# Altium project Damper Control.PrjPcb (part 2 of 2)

## Sheet Interface and Peripherals.SchDoc
size A3; Date: Not shown in title block; ApprovedBy: Not shown in title block; CheckedBy: Not shown in title block; Author: Not shown in title block; CompanyName: Not shown in title block; Engineer: Not shown in title block; Organization: Not shown in title block; Address1: Not shown in title block; Address2: Not shown in title block; Address3: Not shown in title block; Address4: Not shown in title block; DocumentNumber: 4; Revision: Use project parameter SCH_Rev; SheetNumber: 4; SheetTotal: 5; PageSetup: Record=PageOptions¦CenterHorizontal=True¦CenterVertical=True¦PrintScale=0.69¦XCorrection=1.00¦YCorrection=1.00¦PrintKind=0¦BorderSize=5000000¦LeftOffset=0¦BottomOffset=0¦Orientation=2¦PaperLength=1000¦PaperWidth=1000¦Scale=100¦PaperSource=15¦PrintQuality=600¦MediaType=1¦DitherType=10¦PaperKind=Letter¦PrintScaleMode=1
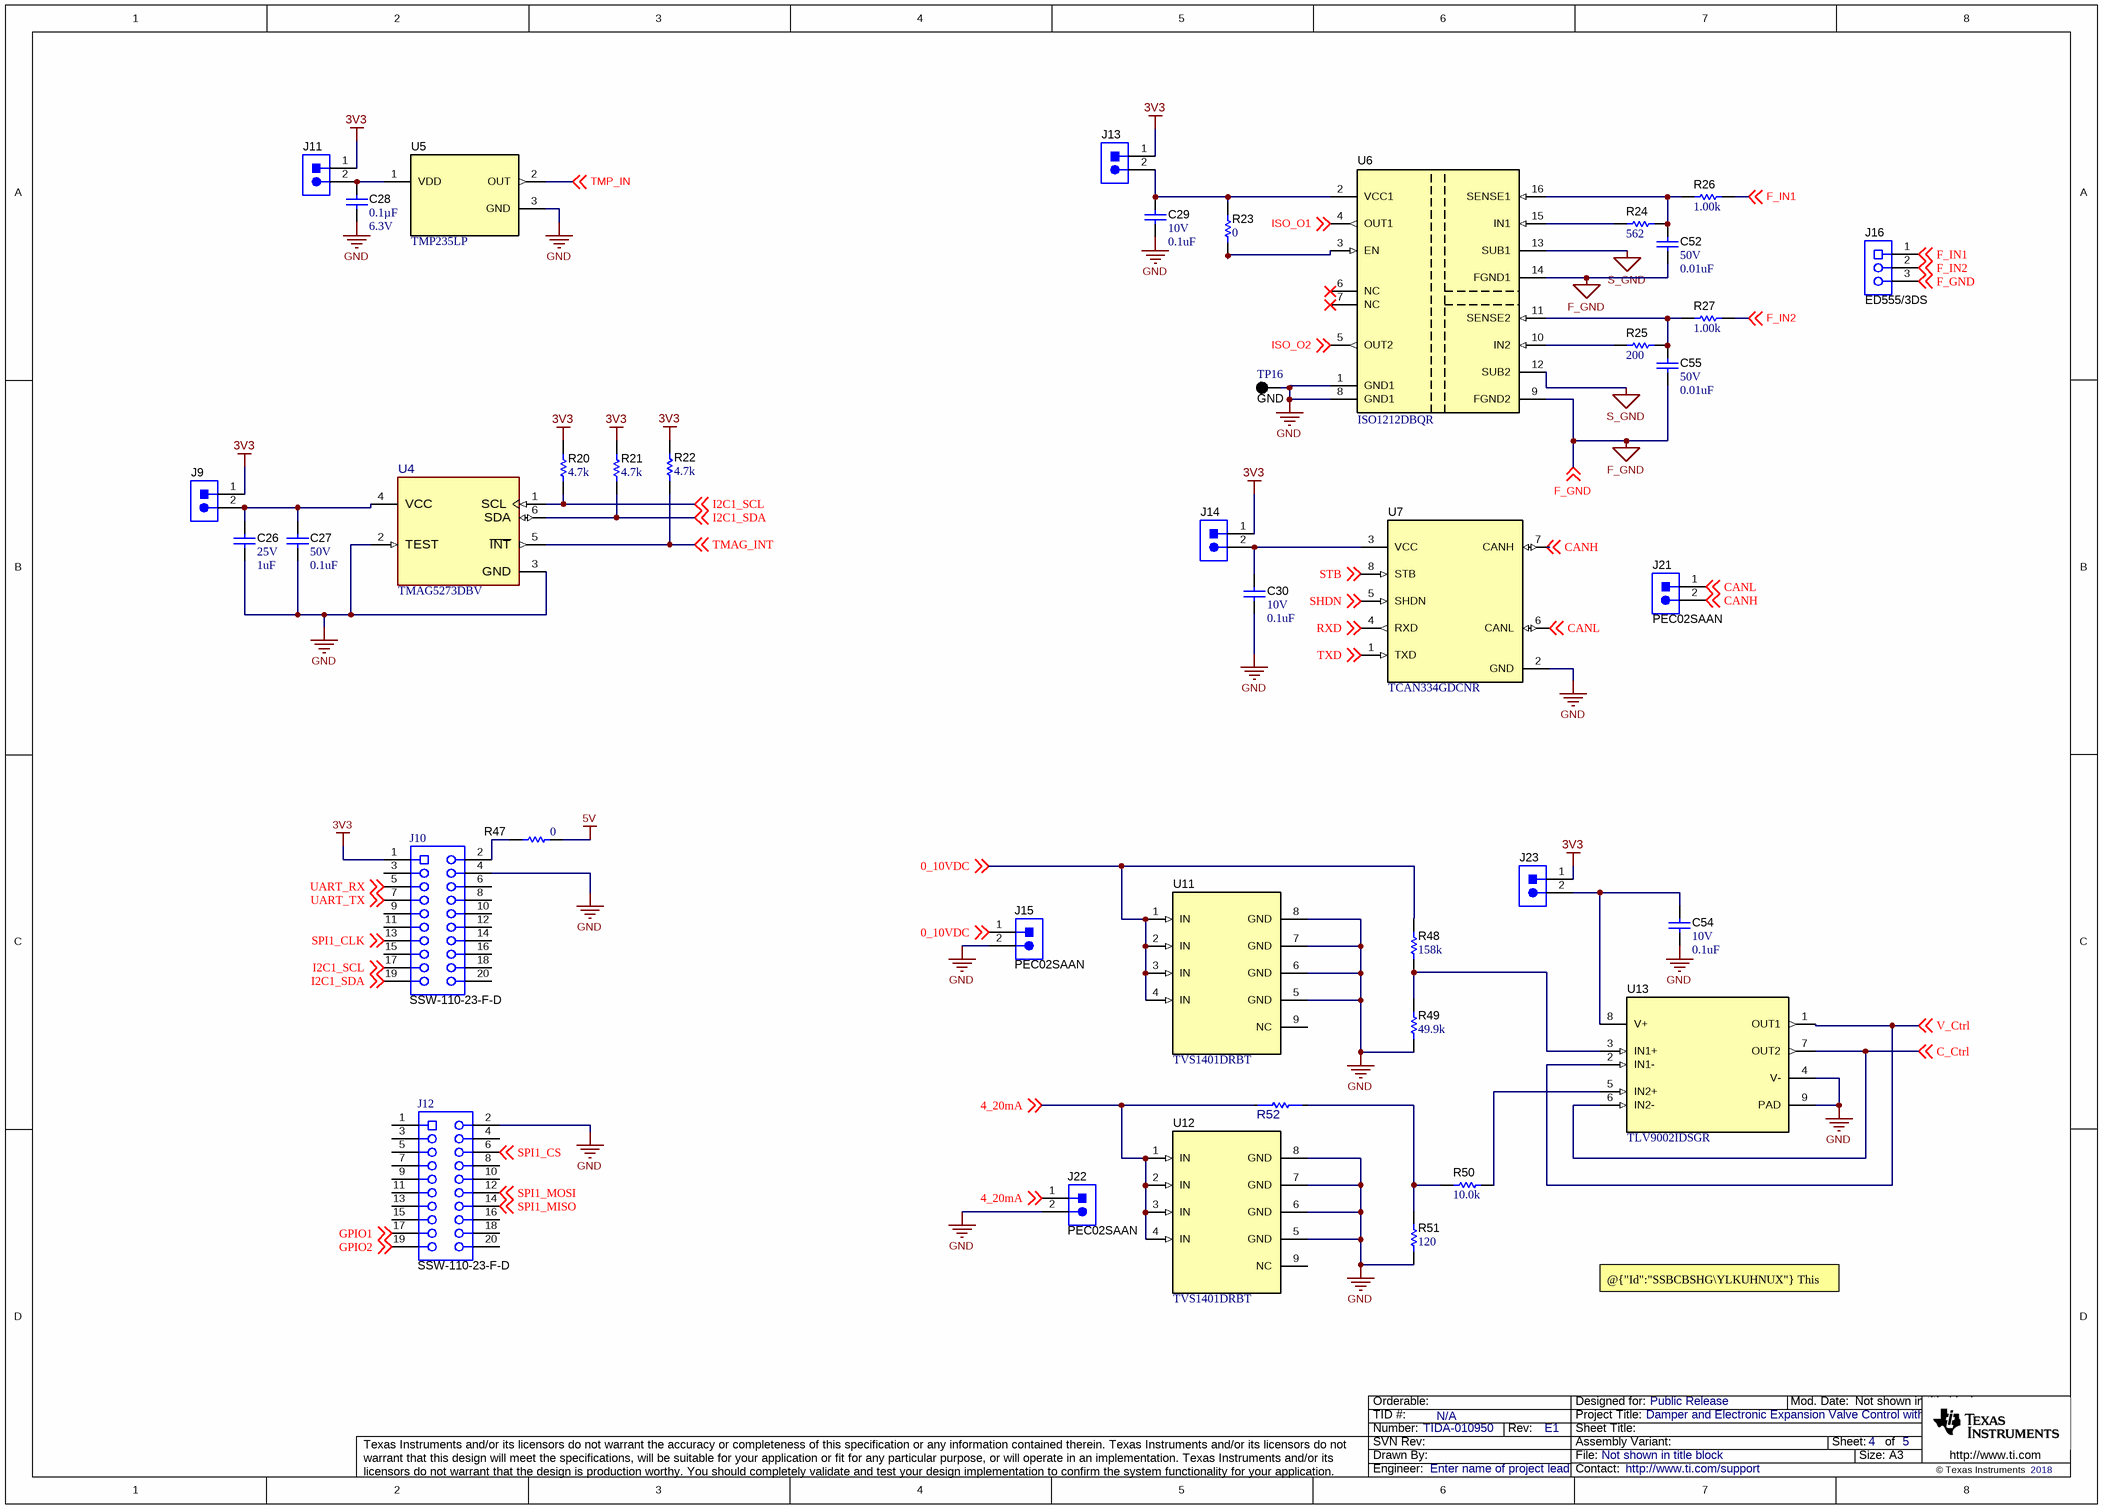
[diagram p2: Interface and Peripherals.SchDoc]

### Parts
(Parts that share a designator on the sheet are numbered #1, #2 ... from top to bottom, then left to right.)
C26  VDC_V: 25V  ValueDisplayed: 1uF  [0402]  (hidden comment: GRM155R61E105KA12D)
C27  VDC_V: 50V  ValueDisplayed: 0.1uF  [0402]  (hidden comment: GRM155R71H104ME14D)
C28  ValueDisplayed: 0.1µF  VDC_V: 6.3V  [0603]  (hidden comment: C0603C104K9PAC7867)
C29  VDC_V: 10V  ValueDisplayed: 0.1uF  [0402]  (hidden comment: GRM155R61A104KA01D)
C30  VDC_V: 10V  ValueDisplayed: 0.1uF  [0402]  (hidden comment: GRM155R61A104KA01D)
C52  VDC_V: 50V  ValueDisplayed: 0.01uF  [0402]  (hidden comment: GRM155R71H103KA88D)
C54#1  VDC_V: 10V  ValueDisplayed: 0.1uF  [0402]  (hidden comment: GRM155R61A104KA01D)
C55  VDC_V: 50V  ValueDisplayed: 0.01uF  [0402]  (hidden comment: GRM155R71H103KA88D)
J9  M20-8770246  [Harwin_M20-87702]  (value not drawn)
J10  SSW-110-23-F-D  [CONN_SSW-110-23-F-D]
J11  M20-8770246  [Harwin_M20-87702]  (value not drawn)
J12  SSW-110-23-F-D  [CONN_SSW-110-23-F-D]
J13  M20-8770246  [Harwin_M20-87702]  (value not drawn)
J14  M20-8770246  [Harwin_M20-87702]  (value not drawn)
J15#1  PEC02SAAN  [CONN_PEC02SAAN]
J16  ED555/3DS  [TERM_BLK_ED555-3DS]
J21  PEC02SAAN  [CONN_PEC02SAAN]
J22#1  PEC02SAAN  [CONN_PEC02SAAN]
J23#1  M20-8770246  [Harwin_M20-87702]  (value not drawn)
R20  ValueDisplayed: 4.7k  [0201]  (hidden comment: RC0201JR-7D4K7L)
R21  ValueDisplayed: 4.7k  [0201]  (hidden comment: RC0201JR-7D4K7L)
R22  ValueDisplayed: 4.7k  [0201]  (hidden comment: RC0201JR-7D4K7L)
R23  ValueDisplayed: 0  [0603]  (hidden comment: CRCW06030000Z0EA)
R24  ValueDisplayed: 562  [0805_HV]  (hidden comment: RG2012P-5620-B-T5)
R25  ValueDisplayed: 200  [0603]  (hidden comment: RT0603DRE07200RL)
R26  ValueDisplayed: 1.00k  [1206]  (hidden comment: RP73D2B1K0BTG)
R27  ValueDisplayed: 1.00k  [1206]  (hidden comment: RP73D2B1K0BTG)
R47  ValueDisplayed: 0  [0603]  (hidden comment: CRCW06030000Z0EA)
R48#1  ValueDisplayed: 158k  [0402]  (hidden comment: CRCW0402158KFKED)
R49#1  ValueDisplayed: 49.9k  [0402]  (hidden comment: CRCW040249K9FKED)
R50#1  ValueDisplayed: 10.0k  [0402]  (hidden comment: CRCW040210K0FKED)
R51#1  ValueDisplayed: 120  [2512]  (hidden comment: CRCW2512120RFKEG)
R52#1  TNPW060312K0BYEN  [FP-TNPW060312K0BYEN_0603-MFG]  (value not drawn)
TP16  GND  [Keystone5001]
U4  TMAG5273DBV  [DBV0006A-MFG]
U5  TMP235LP  [LP0003A]
U6  ISO1212DBQR  [DBQ0016A_N]
U7  TCAN334GDCNR  [DCN0008A_N]
U11#1  TVS1401DRBT  [DRB0008A]
U12#1  TVS1401DRBT  [DRB0008A]
U13#1  TLV9002IDSGR  [DSG0008A]

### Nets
3V3: J9.1 J10.1 J11.1 J13.1 J14.1 J23#1.1 R20.2 R21.2 R22.2
5V: R47.2
F_GND: C52.2 C55.2 J16.3 U6.9(FGND2) U6.14(FGND1) ; off-sheet F_GND
GND: C26.2 C27.2 C28.2 C29.2 C30.2 C54#1.1 J10.4 J12.2 J15#1.2 J22#1.2 R49#1.1 R51#1.1 TP16.1 U4.2(TEST) U4.3(GND) U5.3(GND) U6.1(GND1) U6.8(GND1) U7.2(GND) U11#1.5(GND) U11#1.6(GND) U11#1.7(GND) U11#1.8(GND) U12#1.5(GND) U12#1.6(GND) U12#1.7(GND) U12#1.8(GND) U13#1.4(V-) U13#1.9(PAD)
S_GND: U6.12(SUB2) U6.13(SUB1)
0_10VDC: J15#1.1 R48#1.2 U11#1.1(IN) U11#1.2(IN) U11#1.3(IN) U11#1.4(IN) ; off-sheet 0_10VDC
4_20mA: J22#1.1 R52#1.1 U12#1.1(IN) U12#1.2(IN) U12#1.3(IN) U12#1.4(IN) ; off-sheet 4_20mA
C_Ctrl: U13#1.6(IN2-) U13#1.7(OUT2) ; off-sheet C_Ctrl
CANH: J21.2 U7.7(CANH) ; off-sheet CANH
CANL: J21.1 U7.6(CANL) ; off-sheet CANL
F_IN1: J16.1 R26.2 ; off-sheet F_IN1
F_IN2: J16.2 R27.2 ; off-sheet F_IN2
GPIO1: J12.17 ; off-sheet GPIO1
GPIO2: J12.19 ; off-sheet GPIO2
I2C1_SCL: J10.17 R20.1 U4.1(SCL) ; off-sheet I2C1_SCL
I2C1_SDA: J10.19 R21.1 U4.6(SDA) ; off-sheet I2C1_SDA
ISO_O1: U6.4(OUT1) ; off-sheet ISO_O1
ISO_O2: U6.5(OUT2) ; off-sheet ISO_O2
RXD: U7.4(RXD) ; off-sheet RXD
SHDN: U7.5(SHDN) ; off-sheet SHDN
SPI1_CLK: J10.13 ; off-sheet SPI1_CLK
SPI1_CS: J12.6 ; off-sheet SPI1_CS
SPI1_MISO: J12.14 ; off-sheet SPI1_MISO
SPI1_MOSI: J12.12 ; off-sheet SPI1_MOSI
STB: U7.8(STB) ; off-sheet STB
TMAG_INT: R22.1 U4.5(~{INT}) ; off-sheet TMAG_INT
TMP_IN: U5.2(OUT) ; off-sheet TMP_IN
TXD: U7.1(TXD) ; off-sheet TXD
UART_RX: J10.5 ; off-sheet UART_RX
UART_TX: J10.7 ; off-sheet UART_TX
V_Ctrl: U13#1.1(OUT1) U13#1.2(IN1-) ; off-sheet V_Ctrl
NetC26_1: C26.1 C27.1 J9.2 U4.4(VCC)
NetC28_1: C28.1 J11.2 U5.1(VDD)
NetC29_1: C29.1 J13.2 R23.2 U6.2(VCC1)
NetC30_1: C30.1 J14.2 U7.3(VCC)
NetC52_1: C52.1 R24.2 R26.1 U6.16(SENSE1)
NetC54#1_2: C54#1.2 J23#1.2 U13#1.8(V+)
NetC55_1: C55.1 R25.2 R27.1 U6.11(SENSE2)
NetJ10_2: J10.2 R47.1
NetR23_1: R23.1 U6.3(EN)
NetR24_1: R24.1 U6.15(IN1)
NetR25_1: R25.1 U6.10(IN2)
NetR48#1_1: R48#1.1 R49#1.2 U13#1.3(IN1+)
NetR50#1_1: R50#1.1 U13#1.5(IN2+)
NetR50#1_2: R50#1.2 R51#1.2 R52#1.2

Not connected (* = marked no-connect by the designer): J10 3 6 8 9 10 11 12 14 15 16 18 20; J12 1 3 4 5 7 8 9 10 11 13 15 16 18 20; U6 6(NC)* 7(NC)*; U11#1 9(NC); U12#1 9(NC)

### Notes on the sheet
- @{"Id":"SSBCBSHG\YLKUHNUX"} This should be PRG18BB470MB1RB

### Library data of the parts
C26 = CMP-0006608-2: CAP, CERM, 1 uF, 25 V, +/- 10%, X5R, 0402; Manufacturer: MuRata; TaMin_C: -55°C; Polarized: N; SizeAreaWB_mm2: 3; Value1: Unknown; U/M: EA; Value: 1uF; TaMax_C: 85°C; SizeZ_mm: 0.6; SizeX_mm: 1; SizeY_mm: 0.5; Cap_F: 1µF; AEC Category: Q200
C27 = CMP-0006675-2: CAP, CERM, 0.1 uF, 50 V, +/- 20%, X7R, 0402; Manufacturer: MuRata; TaMin_C: -55°C; Polarized: N; SizeAreaWB_mm2: 3; Value1: Unknown; U/M: EA; Value: 0.1uF; TaMax_C: 125°C; SizeZ_mm: 0.6; SizeX_mm: 1; SizeY_mm: 0.5; Cap_F: 100nF; AEC Category: Q200
C28 = CMP-0085846-1: CAP, CERM, 0.1 µF, 6.3 V,+/- 10%, X5R, 0603; Manufacturer: Kemet; SizeAreaWB_mm2: 4.68; SizeArea_mm2: 1.28; SizeZ_mm: 1; Polarized: N; Cap_F: 100nF; TaMin_C: -55°C; AEC Category: Q200; SizeX_mm: 1.6; Value: 0.1uF; U/M: EA; SizeY_mm: 0.8; TaMax_C: 85°C
C29 C30 C54#1 = CMP-0006562-2: CAP, CERM, 0.1 uF, 10 V, +/- 10%, X5R, 0402; Manufacturer: MuRata; TaMin_C: -55°C; Polarized: N; SizeAreaWB_mm2: 3; Value1: Unknown; U/M: EA; Value: 0.1uF; TaMax_C: 85°C; SizeZ_mm: 0.6; SizeX_mm: 1; SizeY_mm: 0.5; Cap_F: 100nF; AEC Category: Q200
C52 C55 = CMP-0006674-2: CAP, CERM, 0.01 uF, 50 V, +/- 10%, X7R, 0402; Manufacturer: MuRata; TaMin_C: -55°C; Polarized: N; SizeAreaWB_mm2: 3; Value1: Unknown; U/M: EA; Value: 0.01uF; TaMax_C: 125°C; SizeZ_mm: 0.6; SizeX_mm: 1; SizeY_mm: 0.5; Cap_F: 10nF; AEC Category: Q200
J9 J11 J13 J14 J23#1 = CMP-0075288-1: Header, 2.54mm, 2x1, Tin,  SMT; Manufacturer: Harwin; CNHeader: True; Current_A: 3A; Shrouded: N; Gender: Male; Voltage_V: 250V; Row_Count: 1; Pitch_mm: 2.54; CT: False; Cert_UL: Y
J10 J12 = CMP-0075442-1: Connector, Receptacle, 100mil, 10x2, Gold plated, TH; Manufacturer: Samtec; Green_Lifecycle: Active; CompType: Socket Strip; Green_REACh: Passed; CT: True; CNHeader: False
J15#1 J21 J22#1 = CMP-0002337-1: Header, 100mil, 2x1, Tin, TH; Manufacturer: Sullins Connector Solutions; CNHeader: TRUE; Current_A: 3A; Green_Lifecycle: Not Set; Shrouded: N; Gender: Male; Green_REACh: Incomplete; Voltage_V: 1.8kV; Row_Count: 1; Pitch_mm: 2.54; CT: FALSE; Cert_UL: Y
J16 = CMP-0074916-1: Terminal Block, 3.5mm Pitch, 3x1, TH; Manufacturer: On-Shore Technology; Cert_VDE: Y; CNHeader: False; Current_A: 6A; Green_Lifecycle: Active; Shrouded: N; Gender: Female; Green_REACh: Passed; Voltage_V: 150V; Row_Count: 1; Pitch_mm: 3.5; ContactFinish: Brass; CT: True
R20-R22 = CMP-0027242-1: RES, 4.7 k, 5%, 0.05 W, 0201; Manufacturer: Yageo America; Power_W: 50mW; TempCo: 200 ppm/C; Value_Code: 4k70; U/M: EA; Value: 4.7k; EIA_Code: E24; SizeX_mm: 0.6; SizeY_mm: 0.3; SizeZ_mm: 0.26; Value2: 0.05W; SizeArea_mm2: 0.18; AEC Qualified: N; VDC_V: 25V; AEC Category: Q200
R23 R47 = CMP-0025697-4: RES, 0, 5%, 0.1 W, AEC-Q200 Grade 0, 0603; Manufacturer: Vishay-Dale; Power_W: 100mW; TempCo: 200 ppm/C; Value_Code: 0000; Value: 0; EIA_Code: E24; SizeX_mm: 1.6; SizeY_mm: 0.8; SizeZ_mm: 1; Value2: 0.1W; SizeArea_mm2: 1.28; AEC Qualified: Y; VDC_V: 75V; AEC Category: Q200
R24 = CMP-0019016-2: RES, 562, 0.1%, 0.125 W, 0805; Manufacturer: Susumu Co Ltd; Power_W: 125mW; TempCo: 25 ppm/C; Value_Code: 562R; U/M: EA; Value: 562; EIA_Code: E192; SizeX_mm: 2; SizeY_mm: 1.25; SizeZ_mm: 1.45; Value2: 0.125W; SizeArea_mm2: 2.5; VDC_V: 100V; AEC Category: Q200
R25 = CMP-0024912-2: RES, 200, 0.5%, 0.1 W, 0603; Manufacturer: Yageo America; Power_W: 100mW; TempCo: 50 ppm/C; Value_Code: 200R; U/M: EA; Value: 200; EIA_Code: E192; SizeX_mm: 1.6; SizeY_mm: 0.8; SizeZ_mm: 1; Value2: 0.1W; SizeArea_mm2: 1.28; VDC_V: 75V; AEC Category: Q200
R26 R27 = CMP-0018797-2: RES, 1.00 k, 0.1%, 0.25 W, 1206; Manufacturer: TE Connectivity; Power_W: 250mW; TempCo: 15 ppm/C; Value_Code: 1k00; U/M: EA; Value: 1.00k; EIA_Code: E192; Res_ohm: 1k; SizeX_mm: 3.2; SizeY_mm: 1.6; SizeZ_mm: 1.35; Value2: 0.25W; SizeArea_mm2: 5.12; AEC Qualified: N; VDC_V: 200V; AEC Category: Q200
R48#1 = CMP-0026025-3: RES, 158 k, 1%, 0.063 W, AEC-Q200 Grade 0, 0402; Manufacturer: Vishay-Dale; Power_W: 63mW; TempCo: 100 ppm/C; Value: 158k; EIA_Code: E96; SizeX_mm: 1; SizeY_mm: 0.5; SizeZ_mm: 0.6; Value2: 0.063W; AEC Qualified: Y; VDC_V: 50V; AEC Category: Q200; AEC Grade: 0
R49#1 = CMP-0026403-2: RES, 49.9 k, 1%, 0.063 W, AEC-Q200 Grade 0, 0402; Manufacturer: Vishay-Dale; Power_W: 63mW; TempCo: 100 ppm/C; Value_Code: 49k9; Value: 49.9k; EIA_Code: E96; SizeX_mm: 1; SizeY_mm: 0.5; SizeZ_mm: 0.6; Value2: 0.063W; AEC Qualified: Y; VDC_V: 50V; AEC Category: Q200; AEC Grade: 0
R50#1 = CMP-0025958-3: RES, 10.0 k, 1%, 0.063 W, AEC-Q200 Grade 0, 0402; Manufacturer: Vishay-Dale; Power_W: 63mW; TempCo: 100 ppm/C; Value_Code: 10k0; Value: 10.0k; EIA_Code: E96; Res_ohm: 10k; SizeX_mm: 1; SizeY_mm: 0.5; SizeZ_mm: 0.6; Value2: 0.063W; AEC Qualified: Y; VDC_V: 50V; AEC Category: Q200; AEC Grade: 0
R51#1 = CMP-0015444-3: RES, 120, 1%, 1 W, AEC-Q200 Grade 0, 2512; Manufacturer: Vishay-Dale; Power_W: 1W; TempCo: 100 ppm/C; Value_Code: 120R; Value: 120; SizeX_mm: 6.3; SizeY_mm: 3.2; SizeZ_mm: 0.71; SizeArea_mm2: 20.16; AEC Qualified: Y; VDC_V: 500V; AEC Grade: 0; AEC Category: Q200
R52#1 = CMP-0037671-1: 12 kOhms ±0.1% 0.1W, 1/10W Chip Resistor 0603 (1608 Metric) Anti-Sulfur, Automotive AEC-Q200, Moisture Resistant Thin Film; Manufacturer: Vishay; AEC Grade: Grade 0; AEC Qualified: Yes; Power_W: 100mW; Res_ohm: 12k; SizeZ_mm: 0.55mm; TempCo: 10ppm/°C; VDC_V: 75V; Value: 12k
TP16 = CMP-0055138-2: Test Point, Miniature, Black, TH; Manufacturer: Keystone Electronics; ContactFinish: Silver; CNHeader: FALSE; Green_Lifecycle: Active; Green_REACh: Passed; CT: TRUE
U4 = CMP-0090454-1: 3-Axis Linear Hall Effect Sensor With I2C Interface; Manufacturer: Texas Instruments; TaMax_C: +125°C; SizeZ_mm: 1.45mm; AEC Qualified: No; Standoff Height: 0mm; TaMin_C: -40°C; TJmax_C: +150°C; Min Supply Voltage: 2.3V; Max Supply Voltage: 5.5V; Operating Supply Current: 2.8mA
U5 = CMP-0074653-4: Precision Analog Output Temperature Sensor, LP0003A (TO-92-3); Manufacturer: Texas Instruments; SizeZ_mm: 9.33; SizeX_mm: 3.68; SizeY_mm: 5.0; SizeArea_mm2: 18.4; CompType: IC; SizeAreaWB_mm2: 39.76; AEC Category: Q200; AEC Qualified: N; Rating: Catalog
U6 = CMP-0013034-2: ISO1212DBQR, DBQ00016A, DBQ0016A (SSOP-16); Manufacturer: Texas Instruments; SizeX_mm: 6; SizeY_mm: 10; CompType: IC; SizeZ_mm: 1.75; SizeArea_mm2: 60; SizeAreaWB_mm2: 96; U/M: EA
U7 = CMP-0080984-2: 3.3-V CAN Transceivers with CAN FD (Flexible Data Rate), DCN0008A (SOT-23-8); Alternate PartNumber: TCAN334GDCNT; Alternate Manufacturer: Texas Instruments; SizeAreaWB_mm2: 15.21; SizeZ_mm: 1.1; SizeX_mm: 2.9; SizeArea_mm2: 8.41; CompType: IC; AEC Qualified: N; AEC Category: Q200
U11#1 U12#1 = CMP-0083941-3: 14 V Bidirectional Flat-Clamp Surge Protection Device, DRB0008A (VSON-8); Alternate PartNumber: TVS1401DRBR; Manufacturer: Texas Instruments; CompType: IC; SizeZ_mm: 1.0; AEC Qualified: N; SizeAreaWB_mm2: 16.0; SizeY_mm: 3.0; AEC Category: Q200; SizeArea_mm2: 9.0
U13#1 = CMP-0860798-1: 2-Channel, 1MHz, RRIO, 1.8V to 5.5V Operational Amplifier for Cost-Optimized Systems, DSG0008A (WSON-8); Alternate PartNumber: TLV9002IDSGT; Manufacturer: Texas Instruments; AEC Category: Q200; AEC Qualified: N; Rating: Catalog; SizeAreaWB_mm2: 9; SizeX_mm: 2; SizeArea_mm2: 4; CompType: IC; SizeZ_mm: 0.8

## Sheet Damper Control_Hardware.SchDoc
size 431 x 279 mm; Date: Not shown in title block; ApprovedBy: Not shown in title block; CheckedBy: Not shown in title block; Author: Not shown in title block; CompanyName: Not shown in title block; Engineer: Not shown in title block; Organization: Not shown in title block; Address1: Not shown in title block; Address2: Not shown in title block; Address3: Not shown in title block; Address4: Not shown in title block; DocumentNumber: 5; Revision: Use project parameter SCH_Rev; SheetNumber: 5; SheetTotal: 5; PageSetup: Record=PageOptions¦CenterHorizontal=True¦CenterVertical=True¦PrintScale=1.00¦XCorrection=1.00¦YCorrection=1.00¦PrintKind=0¦BorderSize=5000000¦LeftOffset=0¦BottomOffset=0¦Orientation=2¦PaperLength=1000¦PaperWidth=1000¦Scale=100¦PaperSource=15¦PrintQuality=600¦MediaType=1¦DitherType=10¦PaperKind=Letter¦PrintScaleMode=1
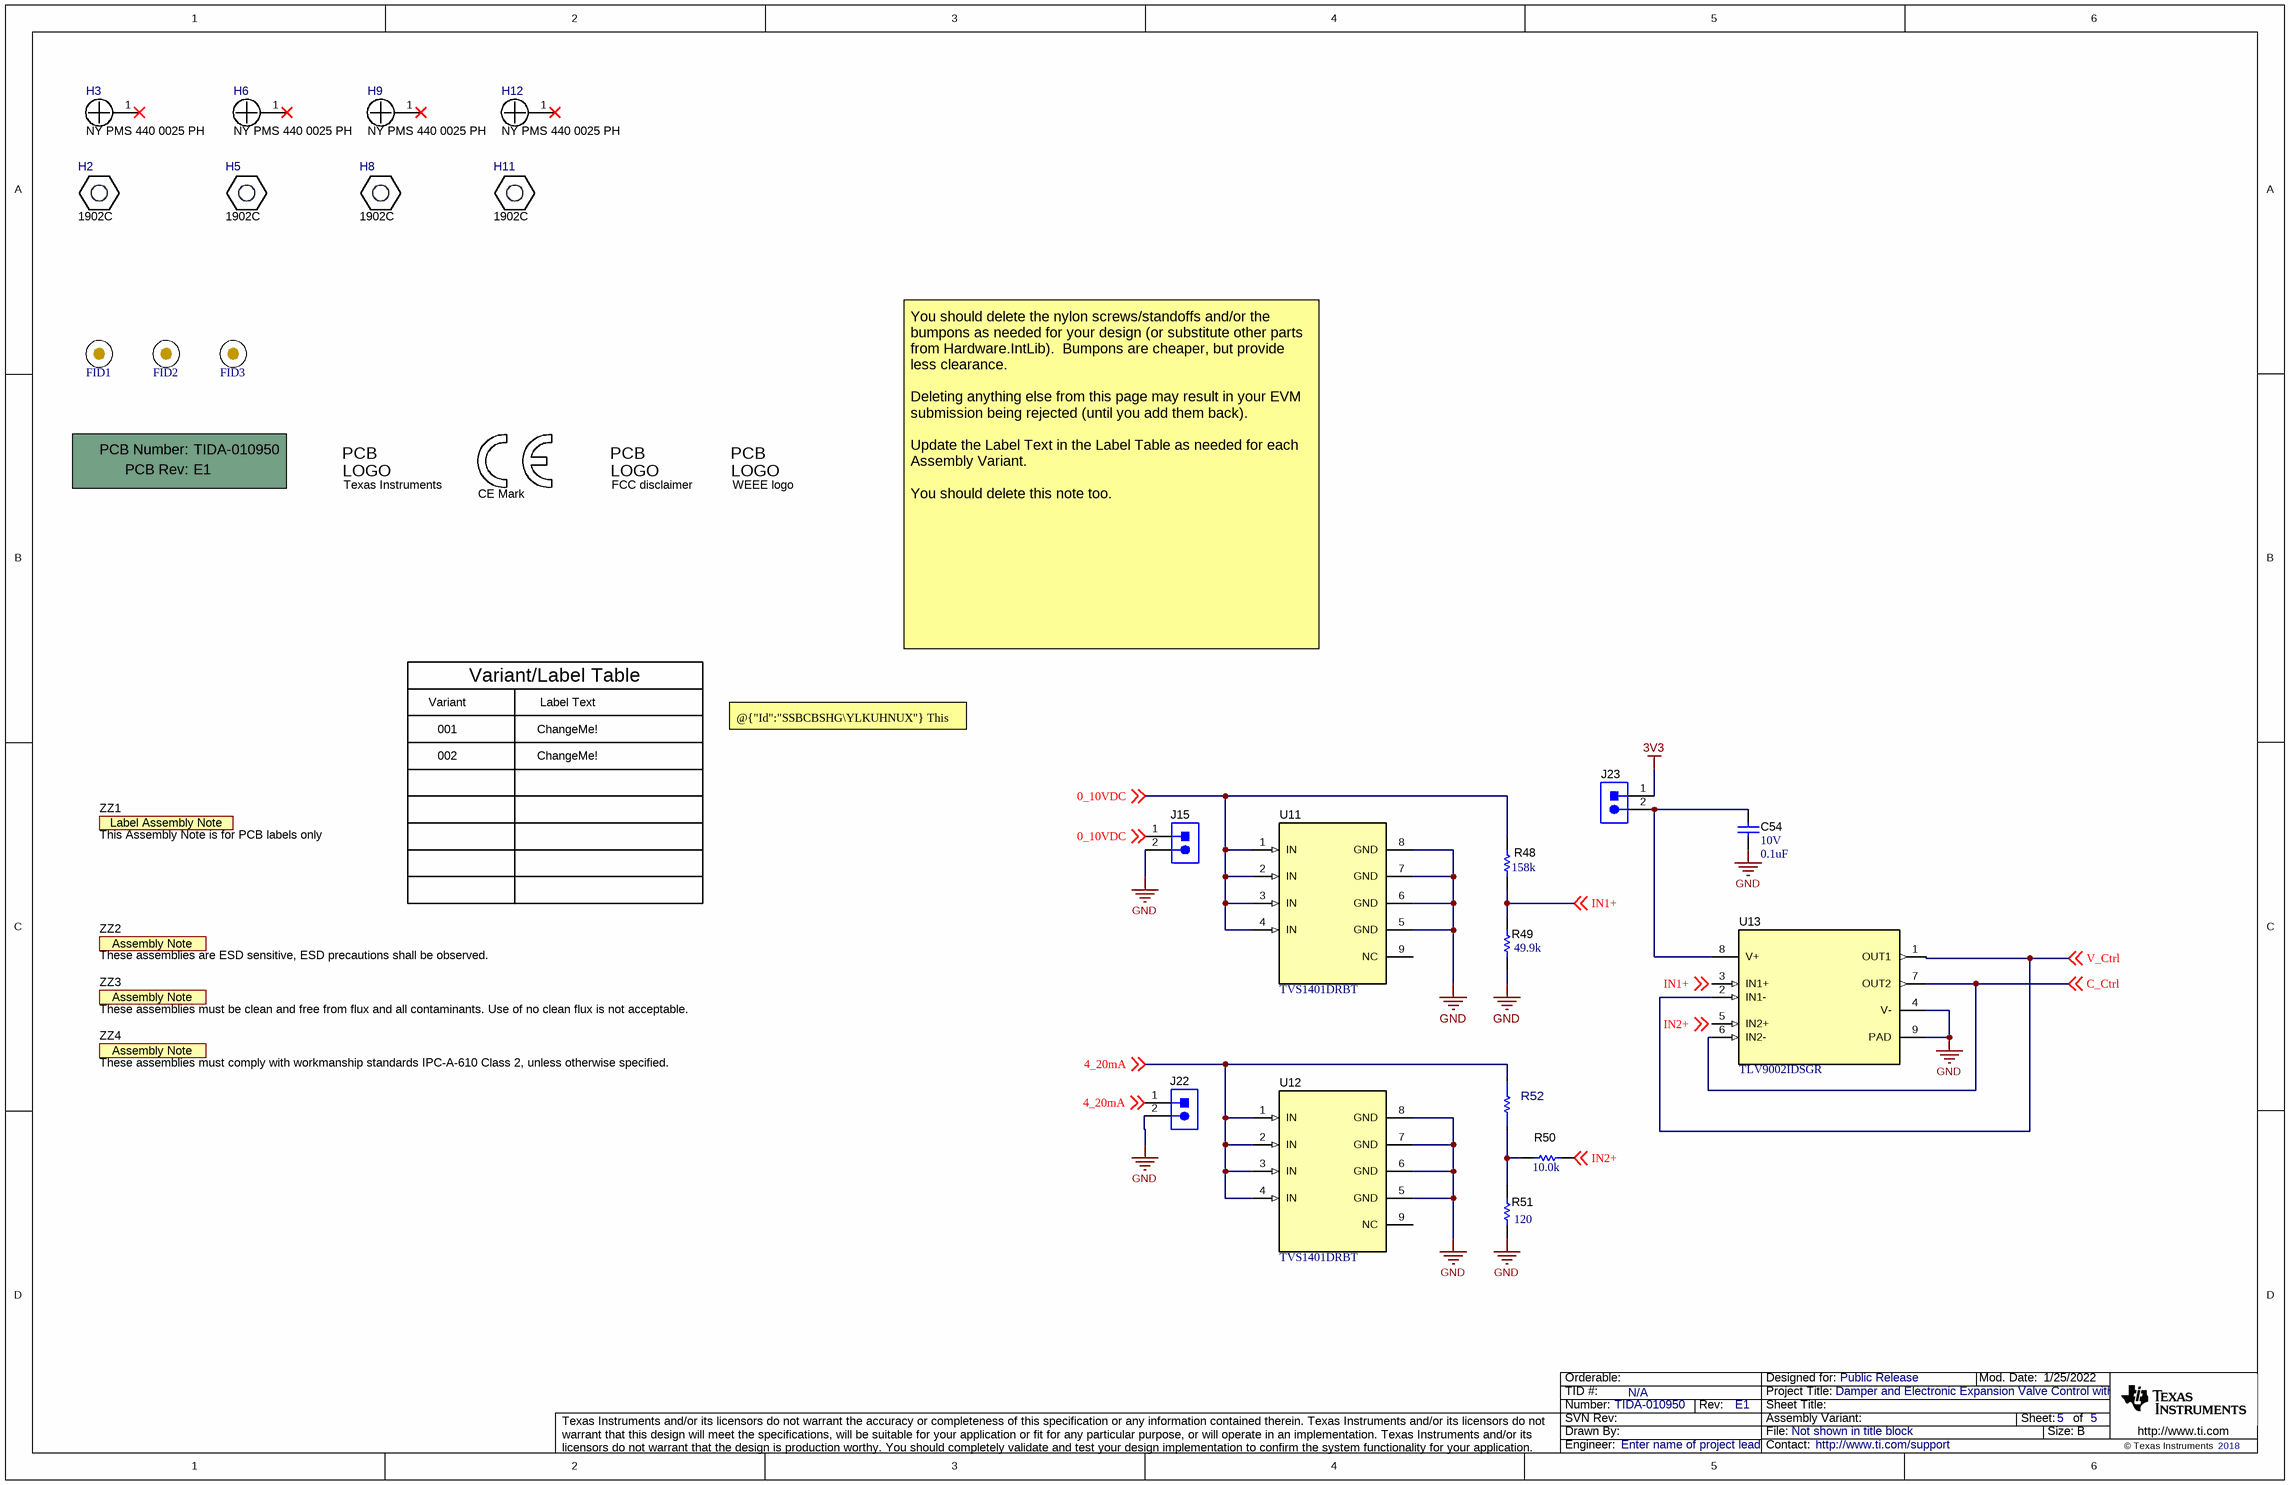
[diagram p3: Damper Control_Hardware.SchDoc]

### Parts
(Parts that share a designator on the sheet are numbered #1, #2 ... from top to bottom, then left to right.)
!PCB1  Printed Circuit Board  (value not drawn)  (mechanical)
C54#2  VDC_V: 10V  ValueDisplayed: 0.1uF  [0402]  (hidden comment: GRM155R61A104KA01D)
FID1  Fiducial  [Fiducial10-20]  (value not drawn)
FID2  Fiducial  [Fiducial10-20]  (value not drawn)
FID3  Fiducial  [Fiducial10-20]  (value not drawn)
H2  1902C  [Keystone_1902C]
H3  NY PMS 440 0025 PH  [NY PMS 440 0025 PH]
H5  1902C  [Keystone_1902C]
H6  NY PMS 440 0025 PH  [NY PMS 440 0025 PH]
H8  1902C  [Keystone_1902C]
H9  NY PMS 440 0025 PH  [NY PMS 440 0025 PH]
H11  1902C  [Keystone_1902C]
H12  NY PMS 440 0025 PH  [NY PMS 440 0025 PH]
J15#2  PEC02SAAN  [CONN_PEC02SAAN]  (value not drawn)
J22#2  PEC02SAAN  [CONN_PEC02SAAN]  (value not drawn)
J23#2  M20-8770246  [Harwin_M20-87702]  (value not drawn)
Logo1  Texas Instruments  [TI_Stacked_Overlay_Small]  (no BOM)
Logo2  CE Mark  [CE_Mark_5mm]  (no BOM)
Logo3  FCC disclaimer  [FCC_disclaimer]  (no BOM)
Logo4  WEEE logo  [WEEE_Minimum]  (no BOM)
R48#2  ValueDisplayed: 158k  [0402]  (hidden comment: CRCW0402158KFKED)
R49#2  ValueDisplayed: 49.9k  [0402]  (hidden comment: CRCW040249K9FKED)
R50#2  ValueDisplayed: 10.0k  [0402]  (hidden comment: CRCW040210K0FKED)
R51#2  ValueDisplayed: 120  [2512]  (hidden comment: CRCW2512120RFKEG)
R52#2  TNPW060312K0BYEN  [FP-TNPW060312K0BYEN_0603-MFG]  (value not drawn)
U11#2  TVS1401DRBT  [DRB0008A]
U12#2  TVS1401DRBT  [DRB0008A]
U13#2  TLV9002IDSGR  [DSG0008A]
ZZ1  This Assembly Note is for PCB labels only  [AssemblyNoteLabel]  (no BOM)
ZZ2  These assemblies are ESD sensitive, ESD precautions shall be observed.  [AssemblyNote]  (no BOM)
ZZ3  These assemblies must be clean and free from flux and all contaminants. Use of no clean flux is not acceptable.  [AssemblyNote]  (no BOM)
ZZ4  These assemblies must comply with workmanship standards IPC-A-610 Class 2, unless otherwise specified.  [AssemblyNote]  (no BOM)

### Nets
3V3: J23#2.1
GND: C54#2.1 J15#2.2 J22#2.2 R49#2.1 R51#2.1 U11#2.5(GND) U11#2.6(GND) U11#2.7(GND) U11#2.8(GND) U12#2.5(GND) U12#2.6(GND) U12#2.7(GND) U12#2.8(GND) U13#2.4(V-) U13#2.9(PAD)
0_10VDC: J15#2.1 R48#2.2 U11#2.1(IN) U11#2.2(IN) U11#2.3(IN) U11#2.4(IN) ; off-sheet 0_10VDC
4_20mA: J22#2.1 R52#2.1 U12#2.1(IN) U12#2.2(IN) U12#2.3(IN) U12#2.4(IN) ; off-sheet 4_20mA
C_Ctrl: U13#2.6(IN2-) U13#2.7(OUT2) ; off-sheet C_Ctrl
IN1+: R48#2.1 R49#2.2 ; off-sheet IN1+
IN2+: R50#2.1 ; off-sheet IN2+
V_Ctrl: U13#2.1(OUT1) U13#2.2(IN1-) ; off-sheet V_Ctrl
NetC54#2_2: C54#2.2 J23#2.2 U13#2.8(V+)
NetR50#2_2: R50#2.2 R51#2.2 R52#2.2

Not connected (* = marked no-connect by the designer): H3 1*; H6 1*; H9 1*; H12 1*; U11#2 9(NC); U12#2 9(NC); U13#2 3(IN1+) 5(IN2+)

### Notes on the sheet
- Variant
- Variant/Label Table
- Label Text
- You should delete the nylon screws/standoffs and/or the bumpons as needed for your design (or substitute other parts from Hardware.IntLib).  Bumpons are cheaper, but provide less clearance.
  Deleting anything else from this page may result in your EVM submission being rejected (until you add them back).
  Update the Label Text in the Label Table as needed for each Assembly Variant.
  You should delete this note too.
- 001
- 002
- ChangeMe!
- @{"Id":"SSBCBSHG\YLKUHNUX"} This should be PRG18BB470MB1RB
- Labels drawn without touching a wire or pin: IN1+, IN2+

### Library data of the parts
!PCB1 = CMP-0003618-2: Manufacturer: Any; PartNumber: TIDA-010950
C54#2 = CMP-0006562-2: as C29 on sheet Interface and Peripherals
FID1-FID3 = CMP-0077181-1: Fiducial mark.  There is nothing to buy or mount.
H2 H5 H8 H11 = CMP-0003610-1: Standoff, Hex, 0.5"L #4-40 Nylon; Manufacturer: Keystone; CompType: Hardware
H3 H6 H9 H12 = CMP-0003617-1: Machine Screw, Round, #4-40 x 1/4, Nylon, Philips panhead; Manufacturer: B&F Fastener Supply; CompType: Hardware
J15#2 J22#2 = CMP-0002337-1: as J15#1 on sheet Interface and Peripherals
J23#2 = CMP-0075288-1: as J9 on sheet Interface and Peripherals
Logo1 = CMP-0074838-1: Texas Instrument Corporate Signature; SymbolCreator: a0412235; Lib Reference: TI_Logo
Logo2 = CMP-0074844-1: SymbolCreator: a0412235
Logo3 = CMP-0074847-1: FCC_disclaimer
Logo4 = CMP-0074769-3: Manufacturer: Texas Instruments; CompType: IC; AEC Category: Q200
R48#2 = CMP-0026025-3: as R48#1 on sheet Interface and Peripherals
R49#2 = CMP-0026403-2: as R49#1 on sheet Interface and Peripherals
R50#2 = CMP-0025958-3: as R50#1 on sheet Interface and Peripherals
R51#2 = CMP-0015444-3: as R51#1 on sheet Interface and Peripherals
R52#2 = CMP-0037671-1: as R52#1 on sheet Interface and Peripherals
U11#2 U12#2 = CMP-0083941-3: as U11#1 on sheet Interface and Peripherals
U13#2 = CMP-0860798-1: as U13#1 on sheet Interface and Peripherals
ZZ1 = CMP-0003616-3
ZZ2 = CMP-0077236-1
ZZ3 = CMP-0077237-1
ZZ4 = CMP-0077238-1

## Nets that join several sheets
3V3: Power (C49.1 C51.1 L3.2 R38.2), Damper Control_BlankSheet (11 pins), Interface and Peripherals (9 pins), Damper Control_Hardware (J23#2.1)
5V: Damper Control_BlankSheet (C19.2 L1.2 U2.3), Interface and Peripherals (R47.2)
15VDC: Power (6 pins), Damper Control_BlankSheet (J3.1 J4.1)
GND: Power (33 pins), Damper Control_BlankSheet (48 pins), Interface and Peripherals (29 pins), Damper Control_Hardware (15 pins)
0_10VDC: Interface and Peripherals (6 pins), Damper Control_Hardware (6 pins)
4_20mA: Interface and Peripherals (6 pins), Damper Control_Hardware (6 pins)
C_Ctrl: Damper Control_BlankSheet (U1.23), Interface and Peripherals (U13#1.6 U13#1.7), Damper Control_Hardware (U13#2.6 U13#2.7)
GPIO1: Damper Control_BlankSheet (U1.6), Interface and Peripherals (J12.17)
GPIO2: Damper Control_BlankSheet (U1.7), Interface and Peripherals (J12.19)
I2C1_SCL: Damper Control_BlankSheet (U1.50), Interface and Peripherals (J10.17 R20.1 U4.1)
I2C1_SDA: Damper Control_BlankSheet (U1.51), Interface and Peripherals (J10.19 R21.1 U4.6)
ISO_O1: Damper Control_BlankSheet (U1.37), Interface and Peripherals (U6.4)
ISO_O2: Damper Control_BlankSheet (U1.36), Interface and Peripherals (U6.5)
RXD: Damper Control_BlankSheet (U1.31), Interface and Peripherals (U7.4)
SHDN: Damper Control_BlankSheet (U1.33), Interface and Peripherals (U7.5)
SPI1_CLK: Damper Control_BlankSheet (U1.10 U2.35), Interface and Peripherals (J10.13)
SPI1_CS: Damper Control_BlankSheet (U1.58), Interface and Peripherals (J12.6)
SPI1_MISO: Damper Control_BlankSheet (U1.59 U2.33), Interface and Peripherals (J12.14)
SPI1_MOSI: Damper Control_BlankSheet (U1.60 U2.34), Interface and Peripherals (J12.12)
STB: Damper Control_BlankSheet (U1.34), Interface and Peripherals (U7.8)
TMAG_INT: Damper Control_BlankSheet (U1.53), Interface and Peripherals (R22.1 U4.5)
TMP_IN: Damper Control_BlankSheet (U1.9), Interface and Peripherals (U5.2)
TXD: Damper Control_BlankSheet (U1.30), Interface and Peripherals (U7.1)
UART_RX: Damper Control_BlankSheet (U1.57), Interface and Peripherals (J10.5)
UART_TX: Damper Control_BlankSheet (U1.56), Interface and Peripherals (J10.7)
V_Ctrl: Damper Control_BlankSheet (U1.27), Interface and Peripherals (U13#1.1 U13#1.2), Damper Control_Hardware (U13#2.1 U13#2.2)

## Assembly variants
001: not fitted C26 C27 FID1 FID2 FID3 J9 R7 R12 R22 R23 R46 R52 U4
BLDC Variant: not fitted C10 C11 C13 C26 C27 J3 J5 J6 J9 R6 R7 R8 R12 R22 R23 R46 R52 TP8 TP9 U3 U4
Stepper Variant: not fitted C12 C14 C15 C16 C17 C18 C19 C20 C21 C22 C23 C24 C25 C26 C27 J4 J7 J8 J9 L1 R7 R9 R10 R11 R12 R13 R14 R15 R16 R17 R18 R19 R22 R23 R46 R52 TP1 TP2 TP3 TP4 TP5 TP6 TP10 TP13 TP14 TP15 U2 U4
